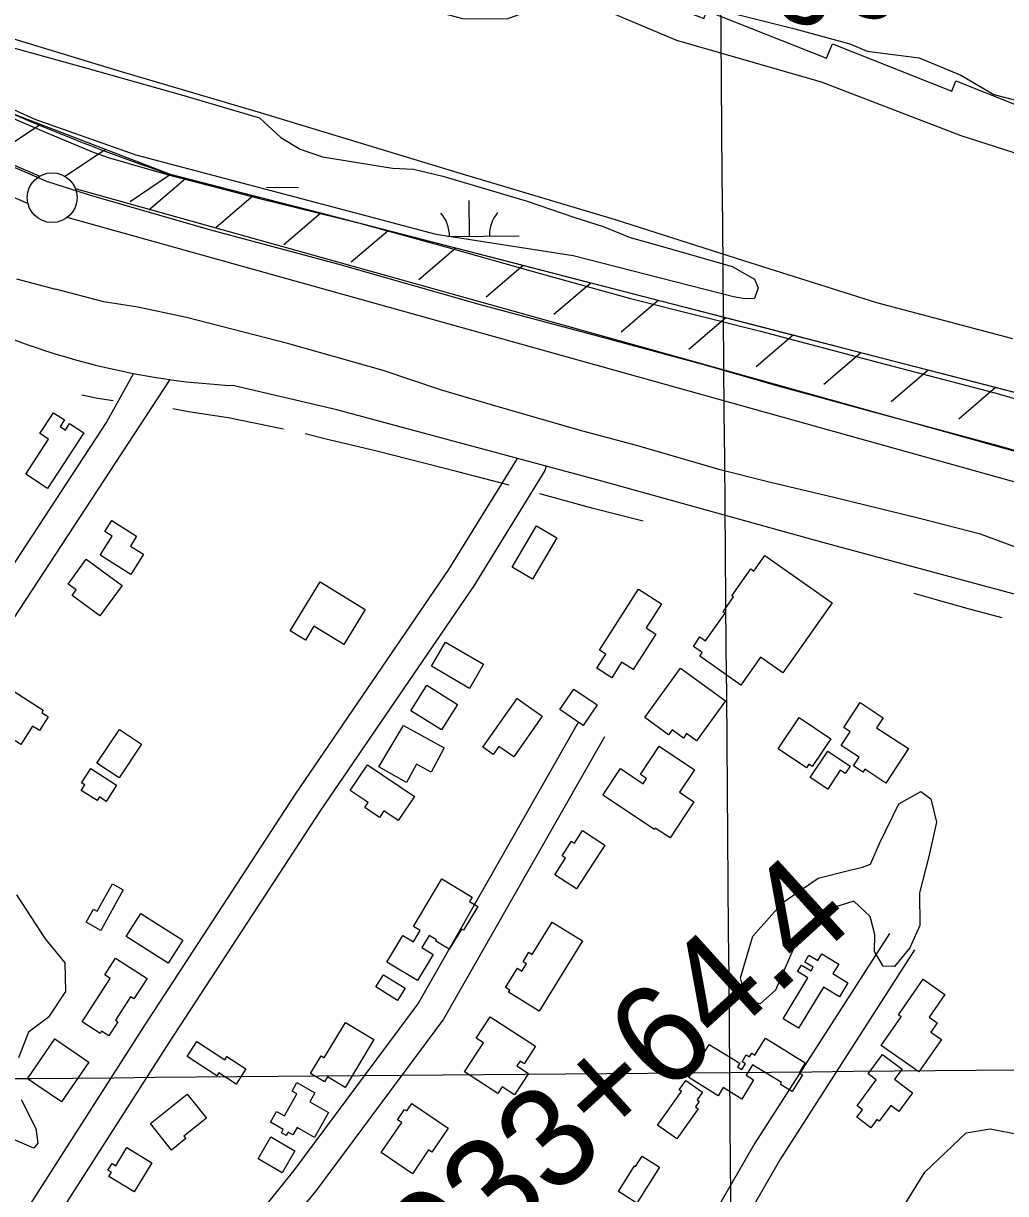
# Model space of a CAD drawing. Extents: x 3567028 to 3605064, y 510945 to 536587.
# Drawn here: x 3586306 to 3587292, y 522418 to 523593 of the extents above; entities that cross this region are included whole.
import ezdxf

# ---------------------------------------------------------------- set-up
doc = ezdxf.new("R2010")
doc.units = 0
for name, color, linetype in [('V-BLDG-OTLN', 7, 'Continuous'), ('V-FLOD-BASE', 7, 'Continuous'), ('V-GRID-MAJR', 7, 'Continuous'), ('V-LEVE-TOET', 7, 'Continuous'), ('V-RIVR-EDGE', 7, 'Continuous'), ('V-RIVR-IDEN', 7, 'Continuous'), ('V-ROAD-CNTR', 7, 'Continuous'), ('V-RRAP-FSHR', 7, 'Continuous'), ('V-RRAP-RVMT', 7, 'Continuous'), ('V-SITE-VEGE', 7, 'Continuous'), ('V-SURV-IDEN', 7, 'Continuous'), ('V-SURV-LINE', 7, 'Continuous'), ('V-TOPO-SHOR', 7, 'Continuous'), ('V-WETL-SWMP', 7, 'Continuous')]:
    doc.layers.add(name, color=color, linetype=linetype)

msp = doc.modelspace()

# ---------------------------------------------------------------- linework, layer by layer
at = {"layer": 'V-BLDG-OTLN'}
for points in [[(3586366.312, 523181.94), (3586329.88, 523126.11100000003), (3586307.911, 523140.447), (3586330.791, 523175.511), (3586322.042, 523181.221), (3586335.702, 523202.151), (3586346.8540000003, 523194.87700000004), (3586342.448, 523188.12700000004), (3586347.773, 523184.651), (3586352.0700000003, 523191.234)], [(3586413.406, 523039.755), (3586382.827, 523058.992), (3586394.879, 523078.153), (3586387.404, 523082.85500000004), (3586394.279, 523093.788), (3586419.224, 523078.098), (3586413.043, 523068.27), (3586426.1520000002, 523060.022)], [(3586796.31, 523047.14400000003), (3586820.964, 523088.7), (3586841.438, 523076.554), (3586816.784, 523035)], [(3586404.648, 523028.8), (3586382.409, 522998.244), (3586354.505, 523018.554), (3586358.687, 523024.303), (3586350.663, 523030.146), (3586368.714, 523054.95300000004)], [(3587050.2290000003, 523058.83), (3587117.754, 523011.24100000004), (3587068.288, 522941.056), (3587045.906, 522956.832), (3587026.036, 522928.641), (3586984.822, 522957.688), (3586987.355, 522961.282), (3586978.43, 522967.571), (3586985.06, 522976.978), (3586990.665, 522973.027), (3587010.2460000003, 523000.808), (3587008.2060000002, 523002.246), (3587018.696, 523017.131), (3587017.123, 523018.24100000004), (3587036.167, 523045.262), (3587039.174, 523043.145)], [(3586573.5670000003, 522983.249), (3586603.614, 523032.444), (3586648.991, 523004.728), (3586627.4220000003, 522969.411), (3586597.3710000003, 522987.76300000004), (3586588.897, 522973.887)], [(3586884.13, 522963.70900000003), (3586923.323, 523024.94), (3586946.3340000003, 523010.213), (3586930.915, 522986.124), (3586940.579, 522979.93700000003), (3586917.828, 522944.38800000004), (3586906.365, 522951.724), (3586896.387, 522936.135), (3586881.529, 522945.643), (3586890.485, 522959.642)], [(3586729.369, 522971.833), (3586767.603, 522949.541), (3586753.5330000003, 522925.413), (3586715.301, 522947.706)], [(3586965.563, 522945.77), (3587010.793, 522913.037), (3586981.633, 522872.745), (3586971.6580000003, 522879.96400000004), (3586968.409, 522875.47500000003), (3586957.014, 522883.72000000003), (3586953.512, 522878.881), (3586929.653, 522896.14900000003)], [(3586263.869, 522894.249), (3586286.137, 522928.809), (3586325.6410000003, 522903.354), (3586324.1410000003, 522901.02400000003), (3586330.615, 522896.852), (3586321.682, 522882.983), (3586314.866, 522887.374), (3586303.031, 522869.018)], [(3586725.429, 522883.74100000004), (3586694.852, 522902.97500000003), (3586710.927, 522928.528), (3586741.503, 522909.291)], [(3586826.659, 522897.58900000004), (3586797.967, 522856.674), (3586783.098, 522867.101), (3586777.501, 522859.12), (3586767.075, 522866.431), (3586801.364, 522915.327)], [(3586881.75, 522908.911), (3586867.906, 522888.283), (3586844.415, 522904.05100000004), (3586858.2600000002, 522924.67600000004)], [(3587162.3510000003, 522885.93), (3587194.294, 522864.987), (3587171.583, 522830.34500000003), (3587150.505, 522844.16500000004), (3587148.603, 522841.26300000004), (3587139.077, 522847.509), (3587144.81, 522856.254), (3587126.8000000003, 522868.061), (3587135.8680000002, 522881.895), (3587129.4760000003, 522886.088), (3587145.838, 522911.045), (3587168.9020000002, 522895.92)], [(3587084.543, 522896.156), (3587116.486, 522874.881), (3587097.806, 522846.836), (3587094.288, 522849.181), (3587091.91, 522845.61100000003), (3587063.49, 522864.547)], [(3586424.252, 522869.45), (3586401.656, 522835.55700000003), (3586379.534, 522850.30700000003), (3586402.129, 522884.197)], [(3586687.4050000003, 522888.007), (3586728.308, 522865.696), (3586715, 522841.3), (3586700.554, 522849.179), (3586690.5, 522830.74700000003), (3586662.719, 522846.52)], [(3586939.383, 522783.84500000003), (3586887.4790000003, 522818.293), (3586905.089, 522844.829), (3586928.066, 522829.579), (3586931.517, 522834.77900000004), (3586925.207, 522838.967), (3586943.977, 522867.25), (3586979.4930000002, 522843.68), (3586964.4960000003, 522821.07800000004), (3586979.039, 522811.42600000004), (3586955.02, 522775.234), (3586940.196, 522785.07)], [(3587095.83, 522835.916), (3587113.389, 522862.202), (3587135.8540000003, 522847.194), (3587130.91, 522839.795), (3587125.909, 522843.137), (3587113.289, 522824.25200000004)], [(3586399.27, 522828.232), (3586388.809, 522811.946), (3586381.938, 522816.359), (3586379.583, 522812.691), (3586363.643, 522822.931), (3586367.239, 522828.531), (3586364.018, 522830.599), (3586373.24, 522844.947)], [(3586651.049, 522848.603), (3586698.2290000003, 522816.90400000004), (3586681.96, 522792.691), (3586667.657, 522802.3), (3586663.358, 522795.9), (3586648.612, 522805.806), (3586651.948, 522810.77400000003), (3586633.8170000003, 522822.956)], [(3586889.475, 522768.143), (3586861.098, 522724.22000000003), (3586839.394, 522738.24), (3586850.1720000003, 522754.92600000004), (3586846.535, 522757.277), (3586856.093, 522772.071), (3586859.044, 522770.16500000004), (3586867.083, 522782.61)], [(3586405.8910000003, 522723.042), (3586383.2490000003, 522682.47500000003), (3586368.718, 522690.586), (3586376.015, 522703.658), (3586379.597, 522701.657), (3586394.947, 522729.151)], [(3586701.504, 522632.06200000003), (3586670.548, 522650.658), (3586686.543, 522677.286), (3586697.275, 522670.841), (3586704.164, 522682.31200000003), (3586697.2090000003, 522686.49), (3586725.898, 522734.243), (3586756.419, 522715.907), (3586753.683, 522711.352), (3586761.838, 522706.456), (3586747.524, 522682.629), (3586745.536, 522683.82300000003), (3586733.326, 522663.499), (3586719.704, 522671.683), (3586720.395, 522672.831), (3586713.114, 522677.206), (3586705.878, 522665.162), (3586717.267, 522658.305)], [(3586451.117, 522649.632), (3586408.9080000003, 522676.291), (3586423.433, 522699.288), (3586465.6380000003, 522672.623)], [(3586867.224, 522672.037), (3586823.6240000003, 522601.477), (3586792.791, 522620.528), (3586793.948, 522622.40400000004), (3586789.713, 522625.021), (3586801.661, 522644.354), (3586806.169, 522641.569), (3586810.705, 522648.907), (3586807.34, 522650.985), (3586813.202, 522660.47000000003), (3586816.6550000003, 522658.336), (3586836.756, 522690.862)], [(3587068.434, 522593.783), (3587093.448, 522634.722), (3587082.929, 522641.14900000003), (3587086.87, 522647.602), (3587096.551, 522641.688), (3587098.8340000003, 522645.425), (3587090.245, 522650.674), (3587094.511, 522657.65400000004), (3587103.326, 522652.272), (3587107.4420000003, 522659.007), (3587124.365, 522648.667), (3587118.495, 522639.06200000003), (3587133.665, 522629.793), (3587125.034, 522615.67), (3587108.972, 522625.48600000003), (3587083.847, 522584.36600000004)], [(3586413.168, 522615.846), (3586397.984, 522592.251), (3586400.608, 522590.561), (3586391.586, 522576.541), (3586384.052, 522581.38800000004), (3586382.565, 522579.08), (3586364.7660000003, 522590.528), (3586392.878, 522634.218), (3586387.414, 522637.737), (3586398.281, 522654.621), (3586429.916, 522634.266), (3586416.629, 522613.618)], [(3586681.311, 522612.145), (3586659.68, 522625.664), (3586667.292, 522637.84500000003), (3586688.9250000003, 522624.329)], [(3587227.52, 522572.971), (3587204.9, 522540.373), (3587166.8850000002, 522566.74700000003), (3587187.06, 522595.827), (3587184.373, 522597.69), (3587209.103, 522633.332), (3587231.1, 522618.07), (3587215.31, 522595.306), (3587223.256, 522589.791), (3587216.764, 522580.434)], [(3586657.648, 522572.869), (3586628.906, 522524.601), (3586610.9560000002, 522535.29000000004), (3586608.041, 522530.39900000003), (3586594.012, 522538.755), (3586604.529, 522556.417), (3586607.8140000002, 522554.45900000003), (3586628.96, 522589.951)], [(3586774.452, 522595.798), (3586820.04, 522566.07300000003), (3586808.588, 522548.51), (3586804.424, 522551.223), (3586801.233, 522546.333), (3586812.725, 522538.83900000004), (3586798.761, 522517.425), (3586786.506, 522525.416), (3586782.095, 522518.65), (3586748.546, 522540.525), (3586767.542, 522569.653), (3586760.431, 522574.294)], [(3586371.325, 522550.042), (3586344.015, 522510.173), (3586309.883, 522533.555), (3586337.193, 522573.424)], [(3587003.395, 522516.352), (3586973.773, 522534.604), (3586994.325, 522567.96), (3587025.0670000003, 522549.018), (3587022.8370000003, 522545.397), (3587027.134, 522542.749), (3587030.654, 522548.463), (3587027.357, 522550.494), (3587031.592, 522557.365), (3587034.826, 522555.373), (3587037.122, 522559.10000000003), (3587040.225, 522557.18700000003), (3587050.698, 522574.185), (3587090.767, 522549.499), (3587084.613, 522539.511), (3587087.91, 522537.477), (3587077.515, 522520.608), (3587065.8370000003, 522527.802), (3587066.949, 522529.60500000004), (3587037.9020000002, 522547.504), (3587031.463, 522537.055), (3587038.932, 522532.45300000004), (3587027.023, 522513.12), (3587008.454, 522524.56200000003)], [(3586500.04, 522536.545), (3586470.131, 522555.776), (3586479.753, 522570.74100000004), (3586507.87, 522552.663), (3586509.932, 522555.874), (3586529.109, 522543.545), (3586519.215, 522528.159), (3586501.8340000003, 522539.333)], [(3587142.836, 522506.37), (3587162.066, 522532.31), (3587153.899, 522538.36600000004), (3587168.356, 522557.865), (3587188.041, 522543.271), (3587180.373, 522532.928), (3587198.5100000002, 522519.481), (3587184.592, 522500.707), (3587176.732, 522506.536), (3587165.1550000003, 522490.92), (3587162.7630000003, 522492.693), (3587156.596, 522484.374), (3587142.543, 522494.795), (3587148.181, 522502.407)], [(3586612.023, 522499.648), (3586597.816, 522474.675), (3586580.498, 522484.53), (3586576.338, 522477.223), (3586571.503, 522479.973), (3586569.598, 522476.629), (3586564.8140000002, 522479.351), (3586566.586, 522482.46400000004), (3586553.669, 522489.814), (3586559.833, 522500.646), (3586567.759, 522496.134), (3586580.33, 522518.228), (3586575.427, 522521.01900000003), (3586580.336, 522529.643), (3586598.4590000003, 522519.33400000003), (3586593.3140000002, 522510.294)], [(3586983.251, 522503.452), (3586961.653, 522473.184), (3586942.363, 522486.955), (3586966.556, 522520.856), (3586964.322, 522522.451), (3586970.969, 522531.765), (3586987.6180000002, 522519.88300000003), (3586982.143, 522512.211), (3586984.224, 522510.724), (3586980.46, 522505.446)], [(3586470.207, 522518.058), (3586489.401, 522493.892), (3586466.787, 522475.931), (3586468.767, 522473.436), (3586454.304, 522461.949), (3586433.132, 522488.61)], [(3586695.644, 522508.768), (3586732.238, 522483.78500000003), (3586715.846, 522459.77400000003), (3586712.5810000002, 522462), (3586696.2490000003, 522438.077), (3586664.988, 522459.42), (3586685.554, 522489.54600000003), (3586681.427, 522492.364), (3586688.46, 522502.66500000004), (3586690.52, 522501.26)], [(3586578.335, 522461.107), (3586565.484, 522439.136), (3586541.299, 522453.284), (3586554.15, 522475.255)], [(3586434.686, 522449.206), (3586416.795, 522419.955), (3586391.406, 522435.485), (3586394.009, 522439.738), (3586390.576, 522441.838), (3586394.636, 522448.473), (3586398.3880000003, 522446.177), (3586409.619, 522464.54000000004)], [(3586903.136, 522420.444), (3586919.3540000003, 522446.071), (3586920.4020000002, 522445.405), (3586926.896, 522455.668), (3586944.3170000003, 522444.641), (3586921.602, 522408.756)]]:
    msp.add_lwpolyline(points, close=True, dxfattribs=at)
at = {"layer": 'V-FLOD-BASE'}
msp.add_lwpolyline([(3587406.645, 523134.041), (3587284.633, 523168.744), (3587158.073, 523203.06700000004), (3587063.67, 523228.906), (3586991.535, 523249.63800000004), (3586886, 523278.034), (3586766.858, 523309.825), (3586621.347, 523351.299), (3586493.9590000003, 523385.21400000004), (3586371.95, 523420.329), (3586329.091, 523434.251), (3586285.029, 523453.14)], dxfattribs=at)
at = {"layer": 'V-GRID-MAJR'}
for points in [[(3587066.1580000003, 516482.603), (3587015.058, 522539.892), (3586963.9280000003, 528600.649), (3586912.799, 534661.42), (3586912.77, 534664.873)], [(3571178.42, 522409.74700000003), (3576457.305, 522452.36100000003), (3581736.185, 522495.743), (3587015.058, 522539.892), (3592293.9250000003, 522584.81), (3597572.785, 522630.495), (3602851.6380000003, 522676.94800000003), (3602851.639, 522676.94800000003)]]:
    msp.add_spline(points, degree=3, dxfattribs=at)
at = {"layer": 'V-LEVE-TOET'}
for points in [[(3586009.534, 523620.259), (3586138.298, 523567.121), (3586251.501, 523516.102), (3586328.651, 523483.416), (3586375.745, 523463.499), (3586390.7830000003, 523458.371), (3586449.9560000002, 523441.384), (3586542.7430000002, 523417.132), (3586642.059, 523392.837), (3586732.33, 523368.101), (3586817.58, 523343.902), (3586915.3680000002, 523316.602), (3587045.7830000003, 523284.055), (3587164.647, 523252.59), (3587281.004, 523222.148), (3587384.3030000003, 523192.298)], [(3586298.724, 523336.594), (3586337.845, 523326.277)], [(3587309.285, 523064.376), (3587266.684, 523080.244), (3587206.9990000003, 523095.72500000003), (3587118.217, 523117.438), (3587056.0130000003, 523131.93200000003), (3587005.353, 523144.84), (3586922.616, 523169.023), (3586865.944, 523183.982), (3586776.684, 523209.717), (3586724.536, 523225.146), (3586666.889, 523244.635), (3586572.109, 523271.413), (3586469.289, 523297.742), (3586420.623, 523308.123), (3586386.4930000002, 523313.382), (3586337.845, 523326.277)]]:
    msp.add_lwpolyline(points, dxfattribs=at)
at = {"layer": 'V-RIVR-EDGE'}
msp.add_lwpolyline([(3586208.152862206, 523876.68874757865), (3586308.9388362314, 523848.82450772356), (3586403.1197732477, 523820.37627359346), (3586454.1115987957, 523805.84234627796), (3586530.3125354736, 523789.4451041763), (3586589.694038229, 523768.88716527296), (3586626.279597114, 523754.9891871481), (3586679.0560628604, 523733.84725397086), (3586722.2555653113, 523724.13520789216), (3586760.018019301, 523700.6290935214), (3586822.9925532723, 523676.4603102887), (3586876.363404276, 523652.91560083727), (3586964.514392, 523613.6763976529), (3587021.516869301, 523602.12924088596), (3587080.3128933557, 523587.57601602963), (3587135.5054952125, 523572.43137476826), (3587152.897047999, 523565.1844508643), (3587205.1088170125, 523558.4517532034), (3587247.0883759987, 523540.93847746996), (3587280.058637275, 523521.6464992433), (3587319.054394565, 523511.3445211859)], dxfattribs=at)
at = {"layer": 'V-ROAD-CNTR'}
for points in [[(3586416.169129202, 523241.497490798), (3586389.2731829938, 523193.4375869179), (3586234.039493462, 522956.46406086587), (3586054.2978529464, 522691.30259118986), (3585897.385166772, 522451.79407020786), (3585885.215191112, 522432.5311087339)], [(3586452.64505625, 523235.43150292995), (3586259.00544353, 522939.8280941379), (3586079.2618030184, 522674.664624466), (3585922.615116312, 522435.5621026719), (3585915.220131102, 522423.8561260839)], [(3588208.4445446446, 522783.4514068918), (3588099.382762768, 522804.1233655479), (3587703.630554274, 522913.5101467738), (3587299.6843621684, 523020.3639330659), (3587108.311744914, 523071.88783001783), (3586886.5001885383, 523133.42970693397), (3586620.4517206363, 523205.02456374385), (3586516.032929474, 523229.3655150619)], [(3586801.577358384, 523156.2796612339), (3586801.5363584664, 523156.128661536), (3586732.680496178, 523044.8068841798), (3586578.5528044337, 522819.2773352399), (3586426.947107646, 522586.486800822), (3586259.133443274, 522324.8513240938)], [(3586830.547300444, 523148.4896768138), (3586829.3643028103, 523144.08868561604), (3586757.8344458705, 523028.444916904), (3586603.5087545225, 522802.6253685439), (3586452.143057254, 522570.20283339), (3586289.233383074, 522316.21234137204)], [(3586863.017235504, 522891.66219047), (3586702.3725567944, 522609.854754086), (3586576.8488078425, 522441.034091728), (3586542.037877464, 522398.03417772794), (3586459.9190417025, 522267.5294387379)], [(3586889.07918338, 522876.804220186), (3586727.5325064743, 522593.4167869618), (3586600.5547604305, 522422.63812852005), (3586566.477828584, 522380.546212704), (3586490.177981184, 522259.28845522)], [(3587175.35861082, 522679.29361520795), (3587040.240881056, 522468.7700362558), (3586930.2981009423, 522278.29241721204), (3586849.0332634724, 522155.8336621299)], [(3587200.6065603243, 522663.0896476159), (3587065.870829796, 522453.1600674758), (3586955.8120499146, 522262.484448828), (3586878.7472040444, 522146.35268109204)]]:
    msp.add_lwpolyline(points, dxfattribs=at)
msp.add_arc((3586553.3903547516, 523953.92119910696), 725.5181021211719, 247.4265338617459, 267.04849219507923, dxfattribs=at)
at = {"layer": 'V-RRAP-FSHR'}
for p, q in [((3586322.8163159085, 523491.49199080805), (3586282.318396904, 523464.210045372)), ((3586388.151185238, 523466.3680410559), (3586347.6532662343, 523439.08609561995)), ((3586453.4860545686, 523441.24409130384), (3586412.987135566, 523413.9621458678)), ((3586468.68502417, 523437.31909915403), (3586431.56509841, 523405.59216260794)), ((3586536.460888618, 523419.8171341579), (3586499.3409628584, 523388.0911976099)), ((3586604.2357530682, 523402.3161691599), (3586567.116827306, 523370.5892326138)), ((3586672.011617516, 523384.814204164), (3586634.8926917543, 523353.0882676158)), ((3586739.787481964, 523367.31323916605), (3586702.667556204, 523335.58630261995)), ((3586807.563346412, 523349.81127416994), (3586770.4434206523, 523318.0853376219)), ((3586875.3392108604, 523332.3103091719), (3586838.2192851, 523300.5833726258)), ((3586943.1140753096, 523314.8083441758), (3586905.995149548, 523283.08140763)), ((3587010.8899397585, 523297.30737917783), (3586973.771013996, 523265.58044263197)), ((3587078.665804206, 523279.80541418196), (3587041.545878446, 523248.07847763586)), ((3587146.441668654, 523262.3044491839), (3587109.321742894, 523230.5775126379)), ((3587214.216533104, 523244.8024841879), (3587177.097607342, 523213.075547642)), ((3587281.992397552, 523227.30151918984), (3587244.8734717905, 523195.574582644))]:
    msp.add_line(p, q, dxfattribs=at)
for points in [[(3586322.8163159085, 523491.49199080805), (3586293.8903737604, 523502.6149685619)], [(3586388.151185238, 523466.3680410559), (3586322.8153159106, 523491.49199080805)], [(3586453.4850545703, 523441.24409130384), (3586388.15018524, 523466.3680410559)], [(3587412.6041363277, 523189.57759463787), (3587413.790133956, 523193.2675872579), (3586453.4850545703, 523441.24409130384)], [(3586468.68502417, 523437.31909915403), (3586453.4850545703, 523441.24409130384)], [(3586536.460888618, 523419.8171341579), (3586468.684024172, 523437.31909915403)], [(3586604.2357530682, 523402.3161691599), (3586536.4598886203, 523419.818134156)], [(3586672.011617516, 523384.814204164), (3586604.23475307, 523402.3161691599)], [(3586739.787481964, 523367.31323916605), (3586672.0106175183, 523384.8152041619)], [(3586807.563346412, 523349.81127416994), (3586739.7864819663, 523367.31323916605)], [(3586875.3392108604, 523332.3103091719), (3586807.562346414, 523349.812274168)], [(3586943.1140753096, 523314.8083441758), (3586875.338210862, 523332.3103091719)], [(3587010.8899397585, 523297.30737917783), (3586943.113075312, 523314.80934417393)], [(3587078.665804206, 523279.80541418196), (3587010.88893976, 523297.30737917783)], [(3587146.441668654, 523262.3044491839), (3587078.664804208, 523279.8064141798)], [(3587214.216533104, 523244.8024841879), (3587146.4406686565, 523262.3044491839)], [(3587281.992397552, 523227.30151918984), (3587214.215533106, 523244.8024841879)], [(3587349.7682620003, 523209.799554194), (3587281.9913975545, 523227.30151918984)]]:
    msp.add_lwpolyline(points, dxfattribs=at)
msp.add_arc((3587102.55908444, 525367.3561372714), 2032.5365211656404, 246.5554118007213, 251.37686457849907, dxfattribs=at)
at = {"layer": 'V-RRAP-RVMT'}
msp.add_lwpolyline([(3586256.6340000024, 523847.56200000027), (3586379.7740000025, 523801.63500000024), (3586384.7350000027, 523815.04600000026), (3586502.6560000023, 523771.0500000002), (3586505.2530000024, 523777.98600000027), (3586627.6620000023, 523732.32600000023), (3586632.1850000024, 523744.42800000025), (3586737.0170000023, 523705.31900000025), (3586736.4960000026, 523704.01900000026), (3586857.8310000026, 523656.07000000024), (3586855.6180000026, 523650.53200000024), (3586988.8660000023, 523597.87500000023), (3586991.8320000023, 523605.38500000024), (3587112.2140000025, 523557.86300000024), (3587117.9920000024, 523572.39500000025), (3587237.8970000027, 523525.00200000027), (3587241.8910000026, 523535.10900000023), (3587363.2730000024, 523487.13400000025)], dxfattribs=at)
at = {"layer": 'V-SITE-VEGE'}
for points in [[(3586230.492, 523824.039), (3586367.534, 523780.494), (3586389.008, 523768.819), (3586417.389, 523741.056), (3586451.822, 523718.76300000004), (3586489.911, 523718.00200000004), (3586557.519, 523709.51900000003), (3586626.991, 523679.97000000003), (3586678.275, 523629.995), (3586718.705, 523605.159), (3586746.7260000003, 523597.94800000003), (3586791.335, 523597.643), (3586833.545, 523612.892), (3586874.644, 523612.61), (3586961.608, 523575.924), (3587106.684, 523534.329), (3587247.163, 523480.235), (3587393.2060000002, 523433.62)], [(3587299.397, 523276.371), (3587162.806, 523312.397), (3587029.262, 523354.412), (3586900.223, 523395.898), (3586743.154, 523442.58900000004), (3586543.574, 523503.103), (3586404.009, 523544.157), (3586247.448, 523591.847)], [(3586298.867, 522717.98600000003), (3586327.457, 522673.954), (3586347.218, 522649.906), (3586348.017, 522621.009), (3586330.904, 522595.222), (3586310.876, 522580.41500000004), (3586300.737, 522554.582)], [(3586303.438, 522512.719), (3586318.184, 522483.72500000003), (3586320.074, 522468.76900000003), (3586316.056, 522463.815), (3586278.307, 522480.016)]]:
    msp.add_lwpolyline(points, dxfattribs=at)
for points in [[(3587205.904, 522687.45), (3587195.762, 522664.87700000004), (3587180.318, 522646.33900000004), (3587168.9990000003, 522646.416), (3587160.4420000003, 522661.125), (3587160.561, 522678.439), (3587156.023, 522696.449), (3587139.481, 522711.879), (3587108.781, 522702.099), (3587079.2290000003, 522665.01), (3587060.9560000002, 522622.518), (3587045.545, 522608.641), (3587031.586, 522612.065), (3587025.747, 522634.74700000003), (3587038.021, 522676.614), (3587068.219, 522710.369), (3587103.6780000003, 522734.76300000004), (3587134.365, 522742.545), (3587148.369, 522745.777), (3587156.3850000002, 522749.054), (3587165.179, 522769.636), (3587184.7660000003, 522809.456), (3587206.825, 522821.957), (3587216.764, 522814.563), (3587222.597, 522791.216), (3587215.036, 522756.642), (3587205.461, 522720.083)], [(3587201.1180000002, 522280.613), (3587182.464, 522279.409), (3587155.2630000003, 522294.244), (3587150.7120000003, 522310.25800000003), (3587154.292, 522346.857), (3587180.5640000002, 522390.62700000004), (3587210.864, 522439.695), (3587252.424, 522479.367), (3587276.4220000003, 522483.199), (3587316.326, 522475.599), (3587333.529, 522459.499), (3587339.321, 522430.16000000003), (3587330.5270000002, 522410.243), (3587311.157, 522401.719), (3587282.323, 522372.615), (3587255.465, 522340.17100000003), (3587233.988, 522315.681), (3587221.227, 522299.784), (3587209.811, 522285.878), (3587206.455, 522281.907)]]:
    msp.add_lwpolyline(points, close=True, dxfattribs=at)
at = {"layer": 'V-SURV-LINE'}
for points in [[(3585564.6828900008, 523765.2230543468), (3586322.0563449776, 523439.6647351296)], [(3586310.2271757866, 523412.09534722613), (3585552.855013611, 523737.65311073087)], [(3586357.780231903, 523427.058175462), (3587437.708323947, 523125.33036010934)], [(3587429.628715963, 523096.43883910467), (3586349.701359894, 523398.166448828)]]:
    msp.add_lwpolyline(points, dxfattribs=at)
msp.add_circle((3586334.503710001, 523417.98670000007), 25, dxfattribs=at)
at = {"layer": 'V-TOPO-SHOR'}
for points in [[(3586395.723, 523213.995), (3586380.244, 523216.532), (3586364.466, 523219.68)], [(3586566.907, 523185.47500000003), (3586511.38, 523197.099), (3586471.313, 523203.147), (3586455.531, 523205.989)], [(3586793.506, 523129.226), (3586741.9420000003, 523142.647), (3586660.65, 523163.563), (3586612.414, 523174.831), (3586588.448, 523180.768)], [(3586927.8710000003, 523093.362), (3586877.8200000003, 523105.859), (3586824.1380000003, 523120.811)], [(3587288.495, 522996.08400000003), (3587255.74, 523004.816), (3587221.165, 523014.473), (3587200.241, 523020.694)]]:
    msp.add_lwpolyline(points, dxfattribs=at)
at = {"layer": 'V-WETL-SWMP'}
for p, q in [((3586549.7992263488, 523428.3263636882), (3586581.798080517, 523428.59631302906)), ((3586753.5361021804, 523379.30155815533), (3586753.2323377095, 523415.3001125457)), ((3586731.8070998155, 523379.1182475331), (3586803.534311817, 523379.72335400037))]:
    msp.add_line(p, q, dxfattribs=at)
msp.add_lwpolyline([(3586257.724, 523578.745), (3586369.403, 523547.835), (3586464.251, 523521.128), (3586542.775, 523498.109), (3586564.1, 523478.548), (3586583.433, 523466.664), (3586605.86, 523458.847), (3586676.291, 523447.635), (3586697.23, 523446.469), (3586726.8170000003, 523439.624), (3586811.457, 523414.52), (3586858.3510000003, 523398.36), (3586887.92, 523388.961), (3586914.924, 523378.04600000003), (3586945.011, 523369.66500000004), (3587017.418, 523348.732), (3587039.8140000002, 523336.316), (3587043.3310000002, 523327.607), (3587039.681, 523316.902), (3587030.481, 523316.455), (3587018.744, 523318.579), (3586857.574, 523359.53500000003), (3586720.2830000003, 523380.913), (3586633.074, 523403.992), (3586418.876, 523460.639), (3586317.449, 523496.588), (3586259.382, 523522.532)], dxfattribs=at)
for centre, radius, start, end in [((3586698.2911378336, 523379.31031745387), 35.24628790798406, 359.71153157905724, 41.25518991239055), ((3586808.7730538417, 523380.2423670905), 35.24628790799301, 139.71152188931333, 181.25518022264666)]:
    msp.add_arc(centre, radius, start, end, dxfattribs=at)

# ---------------------------------------------------------------- texts
at = {"layer": 'V-RIVR-IDEN'}
msp.add_text('Edge ', height=82.99999999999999, rotation=344.42618350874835, dxfattribs=at).set_placement((3586930.8179898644, 523660.94930909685))
at = {"layer": 'V-SURV-IDEN'}
msp.add_text('2933+64.4', height=100.00000000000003, rotation=42.27494567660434, dxfattribs=at).set_placement((3586672.549451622, 522262.7661591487))

doc.saveas('drawing.dxf')
